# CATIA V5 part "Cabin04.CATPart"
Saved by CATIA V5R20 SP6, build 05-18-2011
Part number: Cabin04
Bounding box of the stored display mesh (mm): x -71.5 to 71.5, y 0 to 20, z 1520 to 1760
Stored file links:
  E:\#01 CATIA Lecture Materials\#06 DMU\#01 DMU KIN Page01 EX01\#01 CATPart\Cabin04.CATPart
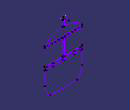
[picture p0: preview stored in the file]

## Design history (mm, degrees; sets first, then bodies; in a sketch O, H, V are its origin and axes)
Set1
  DatumCurve1 "Curve.1 ( *CRV54 - wsp *MASTER -  )"
  DatumCurve2 "Curve.2 ( *CRV55 - wsp *MASTER -  )"
  DatumCurve3 "Curve.3 ( *CRV56 - wsp *MASTER -  )"
  DatumCurve4 "Curve.4 ( *CRV57 - wsp *MASTER -  )"
  DatumCurve5 "Curve.5 ( *CRV58 - wsp *MASTER -  )"
  DatumCurve6 "Curve.6 ( *CRV59 - wsp *MASTER -  )"
  DatumCurve7 "Curve.7 ( *CRV60 - wsp *MASTER -  )"
  DatumCurve8 "Curve.8 ( *CRV61 - wsp *MASTER -  )"
  DatumCurve9 "Curve.9 ( *CRV62 - wsp *MASTER -  )"
  DatumCurve10 "Curve.10 ( *CRV63 - wsp *MASTER -  )"
  DatumCurve11 "Curve.11 ( *CRV64 - wsp *MASTER -  )"
  DatumCurve12 "Curve.12 ( *CRV65 - wsp *MASTER -  )"
  DatumCurve13 "Curve.13 ( *CRV66 - wsp *MASTER -  )"
  DatumCurve14 "Curve.14 ( *CRV67 - wsp *MASTER -  )"
  DatumCurve15 "Curve.15 ( *CRV68 - wsp *MASTER -  )"
  DatumCurve16 "Curve.16 ( *CRV69 - wsp *MASTER -  )"
  DatumCurve17 "Curve.17 ( *CRV70 - wsp *MASTER -  )"
  Line1 "Line.1 ( *LN113 - wsp *MASTER -  )": stored without definition
  Line2 "Line.2 ( *LN114 - wsp *MASTER -  )": stored without definition
  Line3 "Line.3 ( *LN115 - wsp *MASTER -  )": stored without definition
  Line4 "Line.4 ( *LN116 - wsp *MASTER -  )": stored without definition
  Line5 "Line.5 ( *LN117 - wsp *MASTER -  )": stored without definition
  Line6 "Line.6 ( *LN118 - wsp *MASTER -  )": stored without definition
  Line7 "Line.7 ( *LN119 - wsp *MASTER -  )": stored without definition
  Line8 "Line.8 ( *LN120 - wsp *MASTER -  )": stored without definition
  Line9 "Line.9 ( *LN121 - wsp *MASTER -  )": stored without definition
  Line10 "Line.10 ( *LN122 - wsp *MASTER -  )": stored without definition
  Line11 "Line.11 ( *LN123 - wsp *MASTER -  )": stored without definition
  Line12 "Line.12 ( *LN124 - wsp *MASTER -  )": stored without definition
  Line13 "Line.13 ( *LN125 - wsp *MASTER -  )": stored without definition
  Line14 "Line.14 ( *LN126 - wsp *MASTER -  )": stored without definition
  Line15 "Line.15 ( *LN127 - wsp *MASTER -  )": stored without definition
  Line16 "Line.16 ( *LN128 - wsp *MASTER -  )": stored without definition
  Line17 "Line.17 ( *LN129 - wsp *MASTER -  )": stored without definition
  Line18 "Line.18 ( *LN130 - wsp *MASTER -  )": stored without definition
  Line19 "Line.19 ( *LN131 - wsp *MASTER -  )": stored without definition
  Line20 "Line.20 ( *LN132 - wsp *MASTER -  )": stored without definition
  Line21 "Line.21 ( *LN133 - wsp *MASTER -  )": stored without definition
  Line22 "Line.22 ( *LN134 - wsp *MASTER -  )": stored without definition
  Line23 "Line.23 ( *LN135 - wsp *MASTER -  )": stored without definition
  Line24 "Line.24 ( *LN136 - wsp *MASTER -  )": stored without definition
  Line25 "Line.25 ( *LN137 - wsp *MASTER -  )": stored without definition
  Line26 "Line.26 ( *LN138 - wsp *MASTER -  )": stored without definition
  Line27 "Line.27 ( *LN139 - wsp *MASTER -  )": stored without definition
  Line28 "Line.28 ( *LN140 - wsp *MASTER -  )": stored without definition
  Line29 "Line.29 ( *LN141 - wsp *MASTER -  )": stored without definition
  Line30 "Line.30 ( *LN142 - wsp *MASTER -  )": stored without definition
  Line31: stored without definition
Body1 (main body)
